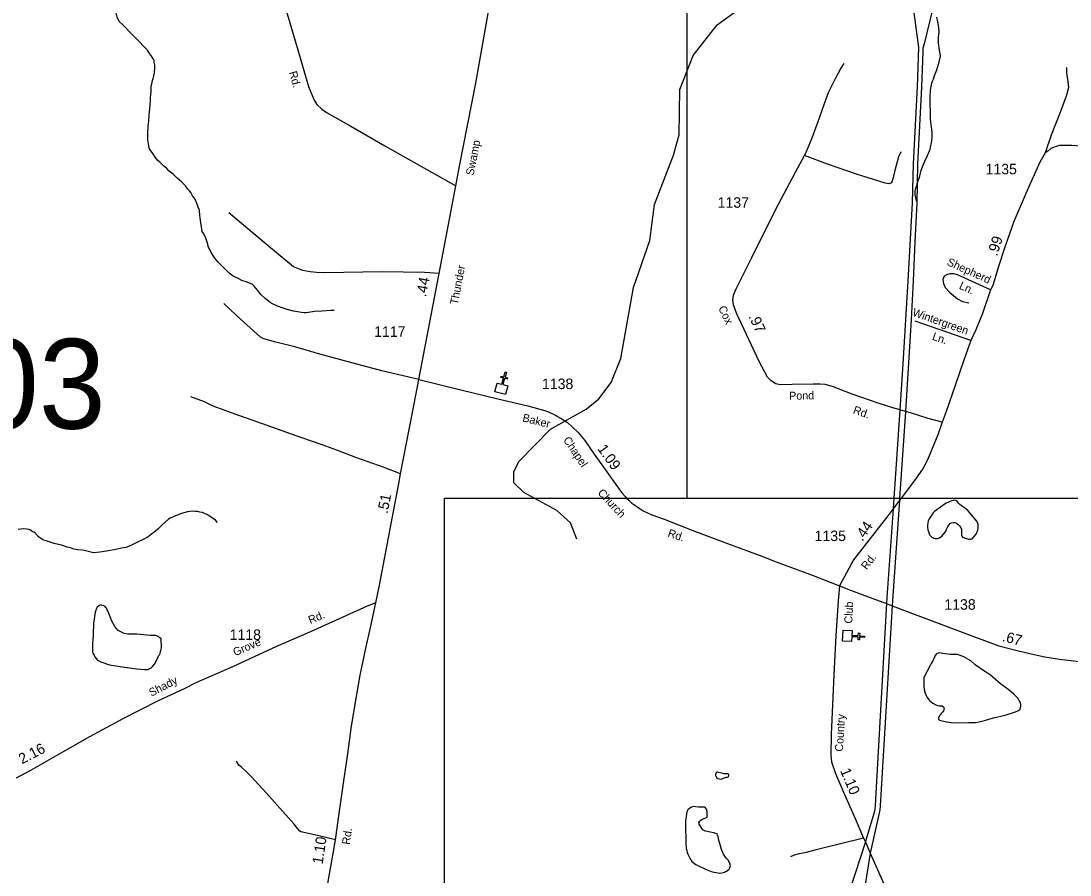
# Model space of a CAD drawing. Extents: x 2206922 to 2357709, y 510027 to 673830.
# Drawn here: x 2263859 to 2276310, y 535777 to 545918 of the extents above; entities that cross this region are included whole.
import ezdxf

# ---------------------------------------------------------------- set-up
doc = ezdxf.new("R2010")
doc.units = 0
for name, color, linetype in [('Exist Cultural Church CELL', 7, 'Continuous'), ('Exist Hydrographic Creek Single Shore', 7, 'Continuous'), ('Exist Hydrographic Misc Water Feature', 7, 'Continuous'), ('Exist Road Non-System Type 51', 7, 'Continuous'), ('Exist Road Non-System Type 51 Label', 7, 'Continuous'), ('Exist Road Secondary Mileage Hundredths English Label', 7, 'Continuous'), ('Exist Road Secondary Structure Standard Bridge Number Label', 7, 'Continuous'), ('Exist Road Secondary Type 51 Attributed', 7, 'Continuous'), ('Exist Road Secondary Type 51 Label', 7, 'Continuous'), ('Exist Road Secondary Type 51 Number Label', 7, 'Continuous'), ('Exist Utilities Electrical Transmission Line', 7, 'Continuous'), ('Map Preparation Inset Cut Line', 7, 'Continuous')]:
    doc.layers.add(name, color=color, linetype=linetype)

msp = doc.modelspace()

# ---------------------------------------------------------------- linework, layer by layer
at = {"layer": 'Exist Cultural Church CELL'}
for points in [[(2269510, 541619), (2269565, 541604), (2269585, 541677), (2269554, 541686), (2269558, 541701), (2269589, 541693), (2269605, 541751), (2269620, 541747), (2269604, 541689), (2269635, 541680), (2269631, 541665), (2269600, 541673), (2269580, 541600), (2269636, 541585), (2269608, 541482), (2269482, 541516)], [(2273723, 538679), (2273720, 538622), (2273797, 538619), (2273798, 538651), (2273814, 538650), (2273812, 538618), (2273873, 538615), (2273872, 538599), (2273812, 538602), (2273810, 538570), (2273794, 538571), (2273796, 538603), (2273720, 538606), (2273717, 538549), (2273611, 538554), (2273617, 538684)]]:
    msp.add_lwpolyline(points, close=True, dxfattribs=at)
at = {"layer": 'Exist Hydrographic Creek Single Shore'}
msp.add_lwpolyline([(2270457, 539765), (2270380, 539957), (2270221, 540104), (2269827, 540319), (2269709, 540433), (2269708, 540567), (2269774, 540691), (2270145, 541070), (2270567, 541308), (2270716, 541433), (2270864, 541626), (2270978, 541909), (2271129, 542752), (2271323, 543313), (2271378, 543738), (2271605, 544324), (2271670, 544565), (2271681, 545106), (2271836, 545509), (2272124, 545871), (2272595, 546216), (2272802, 546435), (2272989, 546887), (2273235, 547229)], dxfattribs=at)
at = {"layer": 'Exist Hydrographic Misc Water Feature'}
for points in [[(2265026, 545913), (2264999, 545963), (2264995, 545979), (2264987, 546013), (2264971, 546039), (2264962, 546057), (2264936, 546086), (2264890, 546136)], [(2267576, 542481), (2267536, 542481), (2267431, 542473), (2267343, 542469), (2267273, 542458), (2267241, 542452), (2267219, 542453), (2267187, 542455), (2267163, 542461), (2267093, 542472), (2267017, 542492), (2266993, 542501), (2266958, 542511), (2266916, 542527), (2266852, 542554), (2266816, 542576), (2266781, 542603), (2266755, 542625), (2266710, 542668), (2266665, 542722), (2266628, 542768), (2266616, 542781), (2266604, 542792), (2266580, 542802), (2266534, 542819), (2266488, 542834), (2266436, 542862), (2266377, 542889), (2266331, 542923), (2266278, 542976), (2266242, 543010), (2266198, 543052), (2266161, 543103), (2266116, 543169), (2266096, 543211), (2266084, 543233), (2266070, 543290), (2266055, 543340), (2266029, 543390), (2266010, 543420), (2266004, 543447), (2266002, 543475), (2265990, 543547), (2265981, 543611), (2265978, 543663), (2265978, 543671), (2265962, 543709), (2265937, 543773), (2265913, 543816), (2265895, 543842), (2265874, 543880), (2265860, 543900), (2265840, 543922), (2265812, 543959), (2265767, 544003), (2265709, 544056), (2265664, 544098), (2265618, 544133), (2265590, 544165), (2265552, 544197), (2265507, 544241), (2265483, 544260), (2265453, 544300), (2265430, 544334), (2265418, 544358), (2265400, 544376), (2265384, 544399), (2265376, 544437), (2265365, 544505), (2265364, 544581), (2265367, 544669), (2265376, 544731), (2265382, 544805), (2265389, 544873), (2265392, 544927), (2265395, 544963), (2265398, 545011), (2265403, 545083), (2265403, 545145), (2265412, 545171), (2265422, 545213), (2265426, 545235), (2265436, 545265), (2265443, 545301), (2265445, 545323), (2265449, 545341), (2265449, 545373), (2265448, 545399), (2265440, 545429), (2265438, 545447), (2265432, 545463), (2265417, 545485), (2265413, 545497), (2265389, 545529), (2265360, 545572), (2265314, 545620), (2265266, 545671), (2265163, 545775), (2265068, 545872), (2265026, 545913)], [(2274489, 543779), (2274484, 543803), (2274472, 543855), (2274472, 543896), (2274482, 543933), (2274491, 543963), (2274501, 543999), (2274508, 544019), (2274518, 544053), (2274528, 544081), (2274545, 544141), (2274563, 544198), (2274588, 544252), (2274617, 544320), (2274631, 544350), (2274641, 544374), (2274649, 544394), (2274653, 544412), (2274658, 544438), (2274666, 544470), (2274672, 544494), (2274675, 544542), (2274673, 544588), (2274669, 544632), (2274662, 544684), (2274653, 544756), (2274653, 544816), (2274654, 544874), (2274650, 544898), (2274650, 544966), (2274651, 545022), (2274656, 545094), (2274662, 545142), (2274666, 545156), (2274671, 545180), (2274679, 545202), (2274691, 545228), (2274703, 545272), (2274728, 545336), (2274751, 545404), (2274767, 545466), (2274772, 545502), (2274764, 545550), (2274758, 545596), (2274749, 545658), (2274749, 545694), (2274748, 545722), (2274758, 545788), (2274753, 545842), (2274742, 545908), (2274730, 545962)], [(2275068, 540128), (2275022, 540162), (2275004, 540178), (2274988, 540191), (2274972, 540215), (2274968, 540217), (2274956, 540225), (2274937, 540227), (2274922, 540225), (2274896, 540217), (2274840, 540194), (2274773, 540145), (2274701, 540093), (2274687, 540077), (2274675, 540063), (2274662, 540040), (2274640, 540008), (2274628, 539980), (2274622, 539958), (2274619, 539926), (2274619, 539906), (2274623, 539876), (2274629, 539854), (2274638, 539830), (2274642, 539818), (2274654, 539803), (2274670, 539789), (2274686, 539781), (2274692, 539777), (2274708, 539773), (2274718, 539771), (2274736, 539773), (2274760, 539781), (2274790, 539800), (2274818, 539832), (2274835, 539858), (2274843, 539882), (2274851, 539898), (2274865, 539921), (2274875, 539934), (2274889, 539949), (2274894, 539953), (2274902, 539957), (2274926, 539963), (2274944, 539961), (2274964, 539953), (2274977, 539943), (2274990, 539932), (2274996, 539926), (2275013, 539904), (2275021, 539878), (2275023, 539864), (2275021, 539838), (2275021, 539828), (2275021, 539812), (2275026, 539800), (2275034, 539790), (2275058, 539780), (2275104, 539765), (2275128, 539763), (2275148, 539769), (2275174, 539797), (2275195, 539824), (2275217, 539870), (2275222, 539894), (2275219, 539942), (2275204, 539980), (2275121, 540077), (2275097, 540107), (2275076, 540122), (2275068, 540128)], [(2266191, 539963), (2266168, 539991), (2266128, 540018), (2266096, 540038), (2266074, 540054), (2266030, 540075), (2266012, 540081), (2265980, 540085), (2265958, 540093), (2265937, 540095), (2265922, 540095), (2265898, 540096), (2265834, 540090), (2265764, 540071), (2265692, 540040), (2265631, 540014), (2265611, 540004), (2265531, 539931), (2265484, 539884), (2265450, 539856), (2265409, 539826), (2265367, 539793), (2265309, 539761), (2265249, 539732), (2265178, 539696), (2265108, 539667), (2265054, 539657), (2264967, 539640), (2264875, 539621), (2264793, 539610), (2264721, 539604), (2264661, 539617), (2264589, 539634), (2264533, 539640), (2264487, 539645), (2264447, 539661), (2264406, 539671), (2264365, 539684), (2264338, 539694), (2264252, 539713), (2264168, 539740), (2264120, 539758), (2264101, 539770), (2264067, 539793), (2264056, 539807), (2264031, 539833), (2264013, 539847), (2263989, 539861), (2263971, 539872), (2263955, 539878), (2263929, 539884), (2263883, 539886), (2263827, 539879)], [(2265506, 538394), (2265526, 538475), (2265524, 538580), (2265508, 538593), (2265496, 538607), (2265480, 538615), (2265457, 538621), (2265393, 538622), (2265234, 538635), (2265216, 538637), (2265199, 538637), (2265192, 538637), (2265172, 538636), (2265148, 538636), (2265126, 538638), (2265085, 538644), (2265030, 538671), (2265014, 538681), (2264971, 538728), (2264936, 538792), (2264889, 538914), (2264879, 538935), (2264873, 538947), (2264867, 538955), (2264859, 538965), (2264851, 538971), (2264843, 538975), (2264835, 538979), (2264816, 538981), (2264803, 538981), (2264789, 538979), (2264777, 538964), (2264765, 538960), (2264740, 538898), (2264718, 538768), (2264716, 538628), (2264713, 538568), (2264709, 538528), (2264707, 538488), (2264708, 538430), (2264710, 538410), (2264726, 538388), (2264735, 538366), (2264769, 538327), (2264805, 538307), (2264908, 538272), (2265035, 538253), (2265232, 538227), (2265324, 538218), (2265364, 538218), (2265376, 538226), (2265402, 538235), (2265421, 538251), (2265449, 538285), (2265469, 538327), (2265484, 538357), (2265492, 538378), (2265506, 538394)], [(2275289, 538203), (2275186, 538274), (2275132, 538320), (2275049, 538367), (2275019, 538379), (2274973, 538394), (2274889, 538397), (2274829, 538405), (2274799, 538409), (2274783, 538413), (2274765, 538414), (2274747, 538410), (2274733, 538408), (2274727, 538404), (2274721, 538400), (2274711, 538382), (2274707, 538370), (2274686, 538330), (2274662, 538287), (2274651, 538263), (2274577, 538121), (2274576, 538085), (2274576, 538053), (2274577, 538017), (2274581, 537981), (2274593, 537937), (2274603, 537909), (2274614, 537883), (2274630, 537866), (2274642, 537850), (2274664, 537832), (2274684, 537818), (2274716, 537796), (2274741, 537790), (2274763, 537787), (2274791, 537785), (2274809, 537773), (2274813, 537761), (2274817, 537753), (2274813, 537737), (2274809, 537727), (2274801, 537713), (2274782, 537693), (2274774, 537681), (2274769, 537677), (2274764, 537673), (2274754, 537657), (2274748, 537645), (2274750, 537626), (2274762, 537615), (2274845, 537596), (2274935, 537582), (2275106, 537586), (2275188, 537589), (2275232, 537597), (2275296, 537612), (2275404, 537643), (2275542, 537674), (2275653, 537711), (2275683, 537721), (2275697, 537730), (2275713, 537740), (2275722, 537762), (2275726, 537781), (2275726, 537802), (2275722, 537823), (2275691, 537875), (2275641, 537929), (2275571, 537984), (2275486, 538049), (2275393, 538126), (2275365, 538150), (2275331, 538173), (2275289, 538203)], [(2272196, 536925), (2272232, 536937), (2272246, 536938), (2272254, 536942), (2272258, 536946), (2272262, 536954), (2272262, 536962), (2272260, 536968), (2272256, 536973), (2272247, 536978), (2272203, 536977), (2272178, 536985), (2272142, 536996), (2272130, 537000), (2272122, 536998), (2272115, 536994), (2272107, 536986), (2272104, 536976), (2272102, 536964), (2272104, 536954), (2272110, 536946), (2272116, 536940), (2272118, 536928), (2272130, 536922), (2272150, 536918), (2272169, 536915), (2272196, 536925)], [(2272160, 536123), (2272143, 536191), (2272135, 536231), (2272128, 536251), (2272122, 536265), (2272108, 536269), (2272084, 536276), (2272038, 536286), (2272008, 536292), (2271980, 536297), (2271976, 536301), (2271954, 536315), (2271938, 536337), (2271909, 536379), (2271908, 536389), (2271905, 536401), (2271915, 536417), (2271919, 536423), (2271939, 536437), (2271997, 536459), (2272003, 536467), (2272004, 536483), (2272005, 536502), (2272004, 536531), (2271994, 536559), (2271982, 536573), (2271971, 536581), (2271961, 536583), (2271901, 536582), (2271836, 536590), (2271808, 536578), (2271794, 536567), (2271776, 536549), (2271762, 536529), (2271758, 536499), (2271755, 536473), (2271745, 536417), (2271745, 536365), (2271748, 536303), (2271751, 536245), (2271752, 536159), (2271756, 536091), (2271761, 536067), (2271765, 536043), (2271777, 536018), (2271793, 535984), (2271803, 535968), (2271823, 535938), (2271868, 535903), (2271902, 535885), (2271984, 535846), (2272061, 535816), (2272109, 535807), (2272151, 535797), (2272179, 535801), (2272209, 535810), (2272235, 535824), (2272266, 535848), (2272274, 535864), (2272280, 535890), (2272274, 535918), (2272251, 535952), (2272231, 535976), (2272213, 536002), (2272199, 536026), (2272172, 536081), (2272160, 536123)]]:
    msp.add_lwpolyline(points, dxfattribs=at)
at = {"layer": 'Exist Road Non-System Type 51'}
msp.add_line((2275134, 542123), (2274474, 542355), dxfattribs=at)
for points in [[(2273625, 545413), (2273592, 545357), (2273525, 545239), (2273441, 545064), (2273394, 544935), (2273332, 544763), (2273244, 544528), (2273185, 544382), (2273158, 544322)], [(2276268, 545366), (2276269, 545304), (2276286, 545194), (2276293, 545128), (2276267, 545038), (2276197, 544844), (2276088, 544561), (2276014, 544352)], [(2274301, 544364), (2274275, 544304), (2274233, 544144), (2274208, 544044), (2274198, 544018), (2274190, 543997), (2274165, 543983), (2274117, 543991), (2273778, 544100), (2273431, 544216), (2273158, 544322)], [(2268823, 542918), (2268648, 542932), (2268148, 542941), (2267460, 542929), (2267368, 542930), (2267292, 542941), (2267206, 542957), (2267132, 542981), (2267094, 542999), (2266843, 543204), (2266326, 543638)], [(2275368, 542727), (2274974, 542905), (2274932, 542915), (2274884, 542917), (2274844, 542904), (2274816, 542886), (2274799, 542850), (2274809, 542800), (2274830, 542752), (2274884, 542693), (2274973, 542617), (2275033, 542586), (2275111, 542573)], [(2268581, 541659), (2268143, 541765), (2267801, 541856), (2267406, 541962), (2267109, 542047), (2266882, 542106), (2266740, 542145), (2266702, 542162), (2266418, 542419), (2266265, 542563)], [(2268364, 540542), (2268169, 540614), (2267835, 540735), (2267606, 540822), (2267432, 540885), (2267193, 540969), (2266780, 541116), (2266401, 541248), (2266139, 541343), (2266037, 541394), (2265875, 541453)], [(2267592, 536193), (2267393, 536241), (2267199, 536284), (2267182, 536291), (2267164, 536303), (2267145, 536324), (2267100, 536381), (2267034, 536457), (2266899, 536606), (2266774, 536747), (2266677, 536851), (2266596, 536943), (2266541, 537000), (2266475, 537059), (2266445, 537083), (2266416, 537127)], [(2273861, 536214), (2273299, 536076), (2273161, 536042), (2273094, 536027), (2273038, 536012), (2272992, 535993)]]:
    msp.add_lwpolyline(points, dxfattribs=at)
at = {"layer": 'Exist Road Secondary Type 51 Attributed'}
for points in [[(2269021, 543961), (2269063, 544193), (2269256, 545178), (2269469, 546372), (2269647, 547187), (2269728, 547592), (2269795, 547935), (2269829, 548105), (2269933, 548443), (2269953, 548522), (2269958, 548578), (2269958, 548614), (2269953, 548659), (2269942, 548702), (2269928, 548758), (2269870, 548921), (2269805, 549110), (2269768, 549207)], [(2266903, 548738), (2266898, 548574), (2266876, 548131), (2266867, 547851), (2266848, 547489), (2266831, 547171), (2266831, 547081), (2266834, 546977), (2266856, 546793), (2266934, 546356), (2266988, 546109), (2267147, 545574), (2267271, 545140), (2267333, 544986), (2267371, 544927), (2267430, 544869), (2267494, 544828), (2267583, 544775), (2267773, 544667), (2268177, 544435), (2268738, 544118), (2269021, 543961)], [(2277787, 544366), (2276557, 544423), (2276331, 544439), (2276239, 544438), (2276181, 544438), (2276135, 544424), (2276084, 544405), (2276048, 544373), (2276014, 544352), (2275951, 544240), (2275800, 543905), (2275642, 543535), (2275535, 543233), (2275461, 543002), (2275393, 542775), (2275368, 542727), (2275272, 542445), (2275192, 542252), (2275134, 542123), (2275056, 541901), (2274947, 541590), (2274842, 541281), (2274791, 541155)], [(2274791, 541155), (2274627, 541199), (2274418, 541263), (2274358, 541281), (2274292, 541300), (2274194, 541329), (2274045, 541377), (2273724, 541488), (2273492, 541576), (2273405, 541601), (2273343, 541605), (2273261, 541606), (2273012, 541600), (2272872, 541596), (2272818, 541610), (2272763, 541643), (2272721, 541689), (2272621, 541874), (2272352, 542447), (2272315, 542547), (2272309, 542607), (2272318, 542663), (2272349, 542737), (2272532, 543110), (2272816, 543677), (2273054, 544121), (2273158, 544322)], [(2268581, 541659), (2268823, 542918), (2269021, 543961)], [(2268069, 539009), (2268116, 539219), (2268279, 540093), (2268345, 540425), (2268364, 540542), (2268506, 541268), (2268581, 541659)], [(2268581, 541659), (2269078, 541538), (2269520, 541431), (2269876, 541348), (2270087, 541289), (2270181, 541249), (2270282, 541191), (2270345, 541149), (2270405, 541096), (2270471, 541031), (2270553, 540935), (2270663, 540775), (2270812, 540566), (2270898, 540441), (2270991, 540314), (2271034, 540267), (2271048, 540253), (2271072, 540228), (2271111, 540192), (2271158, 540159), (2271195, 540131), (2271244, 540103), (2271345, 540055), (2271492, 540002), (2271835, 539869), (2272243, 539714), (2272654, 539564), (2272823, 539495), (2273262, 539332), (2273576, 539211)], [(2274791, 541155), (2274742, 541004), (2274668, 540822), (2274617, 540707), (2274566, 540609), (2274475, 540478), (2274306, 540253), (2274285, 540226), (2274211, 540127), (2274148, 540043), (2273741, 539518), (2273576, 539211)], [(2273576, 539211), (2273560, 539034), (2273530, 538616), (2273509, 538155), (2273476, 537445), (2273472, 537202), (2273478, 537122), (2273526, 536981), (2273633, 536732), (2273760, 536447), (2273861, 536214), (2273881, 536169), (2273940, 536037), (2274183, 535485), (2274409, 534966), (2274464, 534831), (2274476, 534787), (2274493, 534703), (2274498, 534619), (2274485, 534284), (2274463, 533636), (2274446, 533120), (2274421, 532564)], [(2273576, 539211), (2273704, 539161), (2273969, 539061), (2274131, 538999), (2274199, 538974), (2274378, 538906), (2275190, 538600), (2275467, 538499), (2275650, 538452), (2275812, 538413), (2276011, 538368), (2276185, 538339), (2276517, 538300), (2276837, 538263), (2276951, 538242)], [(2268069, 539009), (2267967, 538968), (2267715, 538853), (2267303, 538670), (2266891, 538489), (2266362, 538246), (2266087, 538127), (2265934, 538059), (2265802, 537993), (2265480, 537841), (2265066, 537633), (2264671, 537418), (2264278, 537192), (2263971, 537019), (2263801, 536925)], [(2267161, 533279), (2267168, 533371), (2267185, 533482), (2267219, 533690), (2267231, 533796), (2267288, 534176), (2267343, 534577), (2267396, 534969), (2267442, 535281), (2267471, 535490), (2267517, 535768), (2267563, 536033), (2267592, 536193), (2267636, 536508), (2267693, 536894), (2267740, 537215), (2267779, 537515), (2267825, 537804), (2267885, 538151), (2267948, 538451), (2268015, 538753), (2268069, 539009)]]:
    msp.add_lwpolyline(points, dxfattribs=at)
at = {"layer": 'Exist Utilities Electrical Transmission Line'}
msp.add_line((2274287, 540253), (2274285, 540226), dxfattribs=at)
for points in [[(2274264, 547242), (2274292, 546967), (2274375, 546516), (2274449, 546073), (2274513, 545602), (2274495, 545136), (2274448, 544222), (2274435, 543758), (2274387, 542830), (2274325, 541846), (2274292, 541300)], [(2274967, 547249), (2274900, 546946), (2274787, 546508), (2274677, 546055), (2274581, 545648), (2274565, 545594), (2274562, 545552), (2274546, 545132), (2274500, 544218), (2274491, 543756), (2274467, 543294), (2274447, 542831), (2274424, 542374), (2274358, 541281)], [(2274292, 541300), (2274292, 541296), (2274220, 540253)], [(2274358, 541281), (2274358, 541275), (2274287, 540253)], [(2274285, 540226), (2274203, 539038), (2274199, 538974)], [(2274220, 540253), (2274211, 540128), (2274211, 540127)], [(2274211, 540127), (2274135, 539072), (2274131, 538999)], [(2274131, 538999), (2273996, 536608), (2273992, 536558), (2273981, 536508), (2273892, 536201), (2273881, 536169)], [(2274199, 538974), (2274056, 536600), (2274052, 536550), (2274041, 536494), (2273945, 536072), (2273940, 536037)], [(2273881, 536169), (2273192, 534050), (2272563, 532131), (2272556, 532110)], [(2273940, 536037), (2273345, 532288), (2273340, 532255)]]:
    msp.add_lwpolyline(points, dxfattribs=at)
at = {"layer": 'Map Preparation Inset Cut Line'}
for p, q in [((2274220, 540253), (2274287, 540253)), ((2274287, 540253), (2274306, 540253))]:
    msp.add_line(p, q, dxfattribs=at)
for points in [[(2282834, 540253), (2282834, 546746), (2271763, 546746), (2271763, 540253)], [(2268884, 521584), (2268884, 540253), (2271763, 540253)], [(2271763, 540253), (2282834, 540253)]]:
    msp.add_lwpolyline(points, dxfattribs=at)

# ---------------------------------------------------------------- texts
at = {"layer": 'Exist Road Non-System Type 51 Label'}
for s, rotation, p in [('Shepherd', 335.6429, (2274841, 543023)), ('Ln.', 335.6429, (2274986, 542742)), ('Wintergreen', 340.661, (2274432, 542420)), ('Ln.', 340.661, (2274667, 542135))]:
    msp.add_text(s, height=95, rotation=rotation, dxfattribs=at).set_placement(p)
at = {"layer": 'Exist Road Secondary Mileage Hundredths English Label'}
for s, rotation, p in [('.99', 72.2601, (2275444, 543119)), ('.44', 79.1178, (2268667, 542635)), ('.97', 295.1568, (2272492, 542410)), ('1.09', 305.4627, (2270696, 540837)), ('.51', 78.5923, (2268209, 540062)), ('.44', 56.0157, (2273846, 539731)), ('.67', 345.6695, (2275498, 538556)), ('2.16', 27.3278, (2263871, 537090)), ('1.10', 293.0591, (2273580, 537016)), ('1.10', 81.587, (2267439, 535900))]:
    msp.add_text(s, height=125, rotation=rotation, dxfattribs=at).set_placement(p)
at = {"layer": 'Exist Road Secondary Structure Standard Bridge Number Label'}
msp.add_text('103', height=1066.3, dxfattribs=at).set_placement((2262485, 541077))
at = {"layer": 'Exist Road Secondary Type 51 Label'}
for s, rotation, p in [('Rd.', 285.921, (2267039, 545308)), ('Swamp', 78.9374, (2269231, 544078)), ('Thunder', 79.0964, (2269043, 542543)), ('Cox', 295.1568, (2272133, 542510)), ('Pond', 1.422, (2272978, 541419)), ('Rd.', 340.9192, (2273728, 541261)), ('Baker', 345.9574, (2269805, 541165)), ('Chapel', 303.6904, (2270291, 540944)), ('Church', 312.9806, (2270698, 540309)), ('Rd.', 341.4436, (2271529, 539799)), ('Rd.', 52.2474, (2273897, 539394)), ('Rd.', 22.654, (2267293, 538756)), ('Club', 87.277, (2273725, 538761)), ('Grove', 23.1768, (2266400, 538374)), ('Shady', 27.5088, (2265408, 537893)), ('Country', 86.7205, (2273614, 537240)), ('Rd.', 81.8794, (2267762, 536133))]:
    msp.add_text(s, height=95, rotation=rotation, dxfattribs=at).set_placement(p)
at = {"layer": 'Exist Road Secondary Type 51 Number Label'}
for s, p in [('1135', (2275308, 544097)), ('1137', (2272128, 543700)), ('1117', (2268051, 542167)), ('1138', (2270043, 541547)), ('1135', (2273279, 539742)), ('1138', (2274819, 538927)), ('1118', (2266336, 538568))]:
    msp.add_text(s, height=125, dxfattribs=at).set_placement(p)

doc.saveas('drawing.dxf')
